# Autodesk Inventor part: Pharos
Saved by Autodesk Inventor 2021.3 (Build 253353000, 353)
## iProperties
Created: 2022-07
Part Number: Pharos
Material: Generic
Document SubType Name: Modeling
Designer: Administrator
Density: 1 g/cm^3
Appearance: Default
Title: Pharos v3
Author: Administrator
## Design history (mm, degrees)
feature "Body1"
feature "Socket Body" [Body]
feature "Shade Ring" [Body]
feature "Shade Ring +Collar" [Body]
feature "Socket" [Body]
feature "Body1 (1)"
feature "Metal Strain Relief" [Body]
feature "Fabric Cord (1)" [Body]
feature "Stem (Threaded)" [Body]
feature "Cap (Threaded)" [Body]
feature "T8-Bulb" [Body]
body "Solid1"
body "Solid2"
body "Solid3"
body "Solid4"
body "Solid5"
body "Solid6"
body "Solid7"
body "Solid8"
body "Solid9"
body "Solid10"
body "Solid11"
